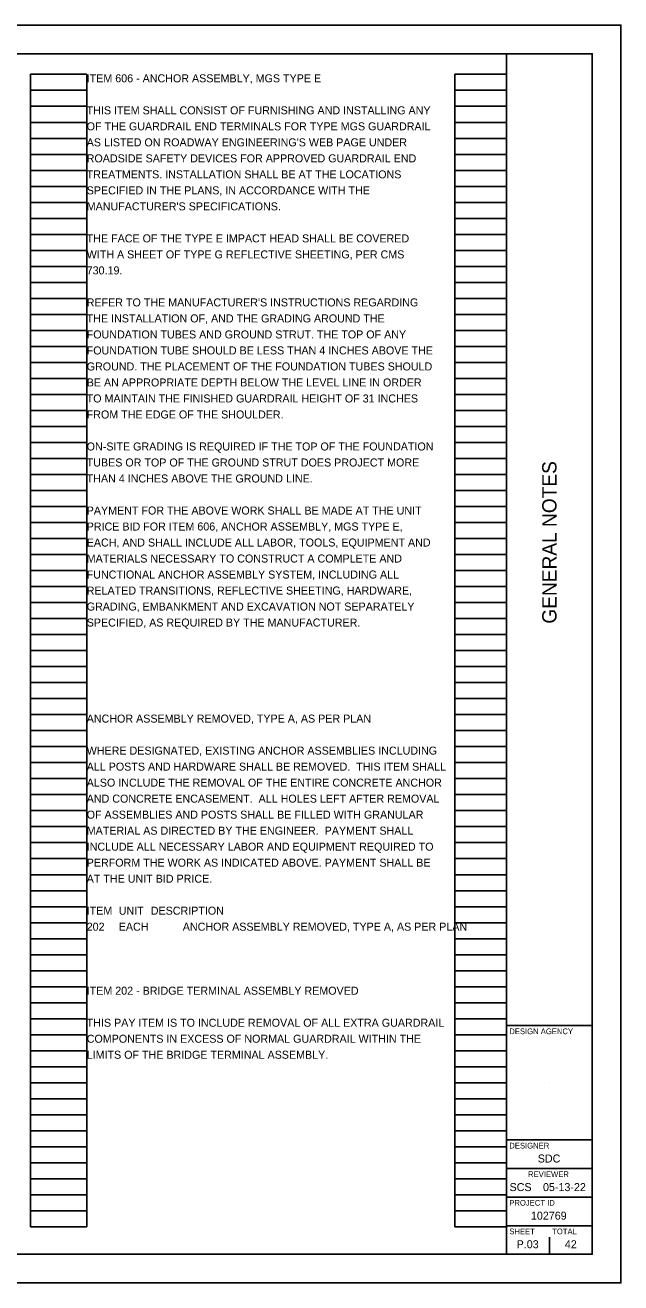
# Model space of a CAD drawing. Extents: x -10.2 to 34, y -7.1 to 22.
# Drawn here: x 23.58 to 34, y 0 to 22 of the extents above; entities that cross this region are included whole.
import ezdxf

# ---------------------------------------------------------------- set-up
doc = ezdxf.new("R2010")
doc.units = 0
for name, color, linetype in [('SH_Border', 7, 'Continuous'), ('SH_Cut_Line', 7, 'Continuous'), ('SH_Data', 7, 'Continuous'), ('SH_Text', 7, 'Continuous')]:
    doc.layers.add(name, color=color, linetype=linetype)

msp = doc.modelspace()

# ---------------------------------------------------------------- linework, layer by layer
at = {"layer": 'SH_Border'}
for p, q in [((32, 0.5), (32, 21.5)), ((32, 4.5), (33.5, 4.5)), ((32, 2.5), (33.5, 2.5)), ((32, 2), (33.5, 2)), ((32, 1.5), (33.5, 1.5)), ((32, 1), (33.5, 1))]:
    msp.add_line(p, q, dxfattribs=at)
msp.add_lwpolyline([(1.5, 21.5), (33.5, 21.5), (33.5, 0.5), (1.5, 0.5)], close=True, dxfattribs=at)
at = {"layer": 'SH_Cut_Line'}
msp.add_lwpolyline([(0, 0), (34, 0), (34, 22), (0, 22)], close=True, dxfattribs=at)
at = {"layer": 'SH_Data'}
for p, q in [((23.68, 0.98), (23.68, 21.14)), ((23.68, 21.14), (24.66, 21.14)), ((24.66, 0.98), (24.66, 21.14)), ((31.1, 0.98), (31.1, 21.14)), ((31.1, 21.14), (32, 21.14)), ((32, 0.98), (32, 21.14)), ((23.68, 20.86), (24.66, 20.86)), ((31.1, 20.86), (32, 20.86)), ((23.68, 20.58), (24.66, 20.58)), ((31.1, 20.58), (32, 20.58)), ((23.68, 20.3), (24.66, 20.3)), ((31.1, 20.3), (32, 20.3)), ((23.68, 20.02), (24.66, 20.02)), ((31.1, 20.02), (32, 20.02)), ((23.68, 19.74), (24.66, 19.74)), ((31.1, 19.74), (32, 19.74)), ((23.68, 19.46), (24.66, 19.46)), ((31.1, 19.46), (32, 19.46)), ((23.68, 19.18), (24.66, 19.18)), ((31.1, 19.18), (32, 19.18)), ((23.68, 18.9), (24.66, 18.9)), ((31.1, 18.9), (32, 18.9)), ((23.68, 18.62), (24.66, 18.62)), ((31.1, 18.62), (32, 18.62)), ((23.68, 18.34), (24.66, 18.34)), ((31.1, 18.34), (32, 18.34)), ((23.68, 18.06), (24.66, 18.06)), ((31.1, 18.06), (32, 18.06)), ((23.68, 17.78), (24.66, 17.78)), ((31.1, 17.78), (32, 17.78)), ((23.68, 17.5), (24.66, 17.5)), ((31.1, 17.5), (32, 17.5)), ((23.68, 17.22), (24.66, 17.22)), ((31.1, 17.22), (32, 17.22)), ((23.68, 16.94), (24.66, 16.94)), ((31.1, 16.94), (32, 16.94)), ((23.68, 16.66), (24.66, 16.66)), ((31.1, 16.66), (32, 16.66)), ((23.68, 16.38), (24.66, 16.38)), ((31.1, 16.38), (32, 16.38)), ((23.68, 16.1), (24.66, 16.1)), ((31.1, 16.1), (32, 16.1)), ((23.68, 15.82), (24.66, 15.82)), ((31.1, 15.82), (32, 15.82)), ((23.68, 15.54), (24.66, 15.54)), ((31.1, 15.54), (32, 15.54)), ((23.68, 15.26), (24.66, 15.26)), ((31.1, 15.26), (32, 15.26)), ((23.68, 14.98), (24.66, 14.98)), ((31.1, 14.98), (32, 14.98)), ((23.68, 14.7), (24.66, 14.7)), ((31.1, 14.7), (32, 14.7)), ((23.68, 14.42), (24.66, 14.42)), ((31.1, 14.42), (32, 14.42)), ((23.68, 14.14), (24.66, 14.14)), ((31.1, 14.14), (32, 14.14)), ((23.68, 13.86), (24.66, 13.86)), ((31.1, 13.86), (32, 13.86)), ((23.68, 13.58), (24.66, 13.58)), ((31.1, 13.58), (32, 13.58)), ((23.68, 13.3), (24.66, 13.3)), ((31.1, 13.3), (32, 13.3)), ((23.68, 13.02), (24.66, 13.02)), ((31.1, 13.02), (32, 13.02)), ((23.68, 12.74), (24.66, 12.74)), ((31.1, 12.74), (32, 12.74)), ((23.68, 12.46), (24.66, 12.46)), ((31.1, 12.46), (32, 12.46)), ((23.68, 12.18), (24.66, 12.18)), ((31.1, 12.18), (32, 12.18)), ((23.68, 11.9), (24.66, 11.9)), ((31.1, 11.9), (32, 11.9)), ((23.68, 11.62), (24.66, 11.62)), ((31.1, 11.62), (32, 11.62)), ((23.68, 11.34), (24.66, 11.34)), ((31.1, 11.34), (32, 11.34)), ((23.68, 11.06), (24.66, 11.06)), ((31.1, 11.06), (32, 11.06)), ((23.68, 10.78), (24.66, 10.78)), ((31.1, 10.78), (32, 10.78)), ((23.68, 10.5), (24.66, 10.5)), ((31.1, 10.5), (32, 10.5)), ((23.68, 10.22), (24.66, 10.22)), ((31.1, 10.22), (32, 10.22)), ((23.68, 9.94), (24.66, 9.94)), ((31.1, 9.94), (32, 9.94)), ((23.68, 9.66), (24.66, 9.66)), ((31.1, 9.66), (32, 9.66)), ((23.68, 9.38), (24.66, 9.38)), ((31.1, 9.38), (32, 9.38)), ((23.68, 9.1), (24.66, 9.1)), ((31.1, 9.1), (32, 9.1)), ((23.68, 8.82), (24.66, 8.82)), ((31.1, 8.82), (32, 8.82)), ((23.68, 8.54), (24.66, 8.54)), ((31.1, 8.54), (32, 8.54)), ((23.68, 8.26), (24.66, 8.26)), ((31.1, 8.26), (32, 8.26)), ((23.68, 7.98), (24.66, 7.98)), ((31.1, 7.98), (32, 7.98)), ((23.68, 7.7), (24.66, 7.7)), ((31.1, 7.7), (32, 7.7)), ((23.68, 7.42), (24.66, 7.42)), ((31.1, 7.42), (32, 7.42)), ((23.68, 7.14), (24.66, 7.14)), ((31.1, 7.14), (32, 7.14)), ((23.68, 6.86), (24.66, 6.86)), ((31.1, 6.86), (32, 6.86)), ((23.68, 6.58), (24.66, 6.58)), ((31.1, 6.58), (32, 6.58)), ((23.68, 6.3), (24.66, 6.3)), ((31.1, 6.3), (32, 6.3)), ((23.68, 6.02), (24.66, 6.02)), ((31.1, 6.02), (32, 6.02)), ((23.68, 5.74), (24.66, 5.74)), ((31.1, 5.74), (32, 5.74)), ((23.68, 5.46), (24.66, 5.46)), ((31.1, 5.46), (32, 5.46)), ((23.68, 5.18), (24.66, 5.18)), ((31.1, 5.18), (32, 5.18)), ((23.68, 4.9), (24.66, 4.9)), ((31.1, 4.9), (32, 4.9)), ((23.68, 4.62), (24.66, 4.62)), ((31.1, 4.62), (32, 4.62)), ((23.68, 4.34), (24.66, 4.34)), ((31.1, 4.34), (32, 4.34)), ((23.68, 4.06), (24.66, 4.06)), ((31.1, 4.06), (32, 4.06)), ((23.68, 3.78), (24.66, 3.78)), ((31.1, 3.78), (32, 3.78)), ((23.68, 3.5), (24.66, 3.5)), ((31.1, 3.5), (32, 3.5)), ((32.75, 3.5), (32.75, 3.5)), ((23.68, 3.22), (24.66, 3.22)), ((31.1, 3.22), (32, 3.22)), ((23.68, 2.94), (24.66, 2.94)), ((31.1, 2.94), (32, 2.94)), ((23.68, 2.66), (24.66, 2.66)), ((31.1, 2.66), (32, 2.66)), ((23.68, 2.38), (24.66, 2.38)), ((31.1, 2.38), (32, 2.38)), ((23.68, 2.1), (24.66, 2.1)), ((31.1, 2.1), (32, 2.1)), ((23.68, 1.82), (24.66, 1.82)), ((31.1, 1.82), (32, 1.82)), ((23.68, 1.54), (24.66, 1.54)), ((31.1, 1.54), (32, 1.54)), ((23.68, 1.26), (24.66, 1.26)), ((31.1, 1.26), (32, 1.26)), ((23.68, 0.98), (24.66, 0.98)), ((31.1, 0.98), (32, 0.98)), ((32.375, 0.675), (32.375, 0.675)), ((32.75, 0.5), (32.75, 0.8))]:
    msp.add_line(p, q, dxfattribs=at)

# ---------------------------------------------------------------- texts
msp.add_text('GENERAL NOTES', height=0.25, rotation=90, dxfattribs=at).set_placement((32.875, 11.531))
for s, height, p in [('DESIGN AGENCY', 0.1, (32.05, 4.35)), ('DESIGNER', 0.1, (32.05, 2.35)), ('SDC', 0.14, (32.547, 2.105)), ('REVIEWER', 0.1, (32.378, 1.85)), ('SCS', 0.14, (32.054, 1.605)), ('05-13-22', 0.14, (32.639, 1.605)), ('PROJECT ID', 0.1, (32.05, 1.35)), ('102769', 0.14, (32.428, 1.105)), ('SHEET', 0.1, (32.05, 0.85)), ('TOTAL', 0.1, (32.8, 0.85)), ('P.03', 0.14, (32.178, 0.605)), ('42', 0.14, (33.021, 0.605))]:
    msp.add_text(s, height=height, dxfattribs=at).set_placement(p)
at = {"layer": 'SH_Text'}
for s, p in [('ITEM 606 - ANCHOR ASSEMBLY, MGS TYPE E', (24.66, 21)), ('THIS ITEM SHALL CONSIST OF FURNISHING AND INSTALLING ANY', (24.66, 20.44)), ('OF THE GUARDRAIL END TERMINALS FOR TYPE MGS GUARDRAIL', (24.66, 20.16)), ("AS LISTED ON ROADWAY ENGINEERING'S WEB PAGE UNDER", (24.66, 19.88)), ('ROADSIDE SAFETY DEVICES FOR APPROVED GUARDRAIL END', (24.66, 19.6)), ('TREATMENTS. INSTALLATION SHALL BE AT THE LOCATIONS', (24.66, 19.32)), ('SPECIFIED IN THE PLANS, IN ACCORDANCE WITH THE', (24.66, 19.04)), ("MANUFACTURER'S SPECIFICATIONS.", (24.66, 18.76)), ('THE FACE OF THE TYPE E IMPACT HEAD SHALL BE COVERED', (24.66, 18.2)), ('WITH A SHEET OF TYPE G REFLECTIVE SHEETING, PER CMS', (24.66, 17.92)), ('730.19.', (24.66, 17.64)), ("REFER TO THE MANUFACTURER'S INSTRUCTIONS REGARDING", (24.66, 17.08)), ('THE INSTALLATION OF, AND THE GRADING AROUND THE', (24.66, 16.8)), ('FOUNDATION TUBES AND GROUND STRUT. THE TOP OF ANY', (24.66, 16.52)), ('FOUNDATION TUBE SHOULD BE LESS THAN 4 INCHES ABOVE THE', (24.66, 16.24)), ('GROUND. THE PLACEMENT OF THE FOUNDATION TUBES SHOULD', (24.66, 15.96)), ('BE AN APPROPRIATE DEPTH BELOW THE LEVEL LINE IN ORDER', (24.66, 15.68)), ('TO MAINTAIN THE FINISHED GUARDRAIL HEIGHT OF 31 INCHES', (24.66, 15.4)), ('FROM THE EDGE OF THE SHOULDER.', (24.66, 15.12)), ('ON-SITE GRADING IS REQUIRED IF THE TOP OF THE FOUNDATION', (24.66, 14.56)), ('TUBES OR TOP OF THE GROUND STRUT DOES PROJECT MORE', (24.66, 14.28)), ('THAN 4 INCHES ABOVE THE GROUND LINE.', (24.66, 14)), ('PAYMENT FOR THE ABOVE WORK SHALL BE MADE AT THE UNIT', (24.66, 13.44)), ('PRICE BID FOR ITEM 606, ANCHOR ASSEMBLY, MGS TYPE E,', (24.66, 13.16)), ('EACH, AND SHALL INCLUDE ALL LABOR, TOOLS, EQUIPMENT AND', (24.66, 12.88)), ('MATERIALS NECESSARY TO CONSTRUCT A COMPLETE AND', (24.66, 12.6)), ('FUNCTIONAL ANCHOR ASSEMBLY SYSTEM, INCLUDING ALL', (24.66, 12.32)), ('RELATED TRANSITIONS, REFLECTIVE SHEETING, HARDWARE,', (24.66, 12.04)), ('GRADING, EMBANKMENT AND EXCAVATION NOT SEPARATELY', (24.66, 11.76)), ('SPECIFIED, AS REQUIRED BY THE MANUFACTURER.', (24.66, 11.48)), ('ANCHOR ASSEMBLY REMOVED, TYPE A, AS PER PLAN', (24.66, 9.8)), ('WHERE DESIGNATED, EXISTING ANCHOR ASSEMBLIES INCLUDING', (24.66, 9.24)), ('ALL POSTS AND HARDWARE SHALL BE REMOVED.  THIS ITEM SHALL', (24.66, 8.96)), ('ALSO INCLUDE THE REMOVAL OF THE ENTIRE CONCRETE ANCHOR', (24.66, 8.68)), ('AND CONCRETE ENCASEMENT.  ALL HOLES LEFT AFTER REMOVAL', (24.66, 8.4)), ('OF ASSEMBLIES AND POSTS SHALL BE FILLED WITH GRANULAR', (24.66, 8.12)), ('MATERIAL AS DIRECTED BY THE ENGINEER.  PAYMENT SHALL', (24.66, 7.84)), ('INCLUDE ALL NECESSARY LABOR AND EQUIPMENT REQUIRED TO', (24.66, 7.56)), ('PERFORM THE WORK AS INDICATED ABOVE. PAYMENT SHALL BE', (24.66, 7.28)), ('AT THE UNIT BID PRICE.', (24.66, 7)), ('ITEM ', (24.66, 6.44)), ('UNIT ', (25.22, 6.44)), ('DESCRIPTION', (25.78, 6.44)), ('202 ', (24.66, 6.16)), ('EACH ', (25.22, 6.16)), ('ANCHOR ASSEMBLY REMOVED, TYPE A, AS PER PLAN', (26.34, 6.16)), ('ITEM 202 - BRIDGE TERMINAL ASSEMBLY REMOVED', (24.66, 5.04)), ('THIS PAY ITEM IS TO INCLUDE REMOVAL OF ALL EXTRA GUARDRAIL', (24.66, 4.48)), ('COMPONENTS IN EXCESS OF NORMAL GUARDRAIL WITHIN THE', (24.66, 4.2)), ('LIMITS OF THE BRIDGE TERMINAL ASSEMBLY.', (24.66, 3.92))]:
    msp.add_text(s, height=0.14, dxfattribs=at).set_placement(p)

doc.saveas('drawing.dxf')
